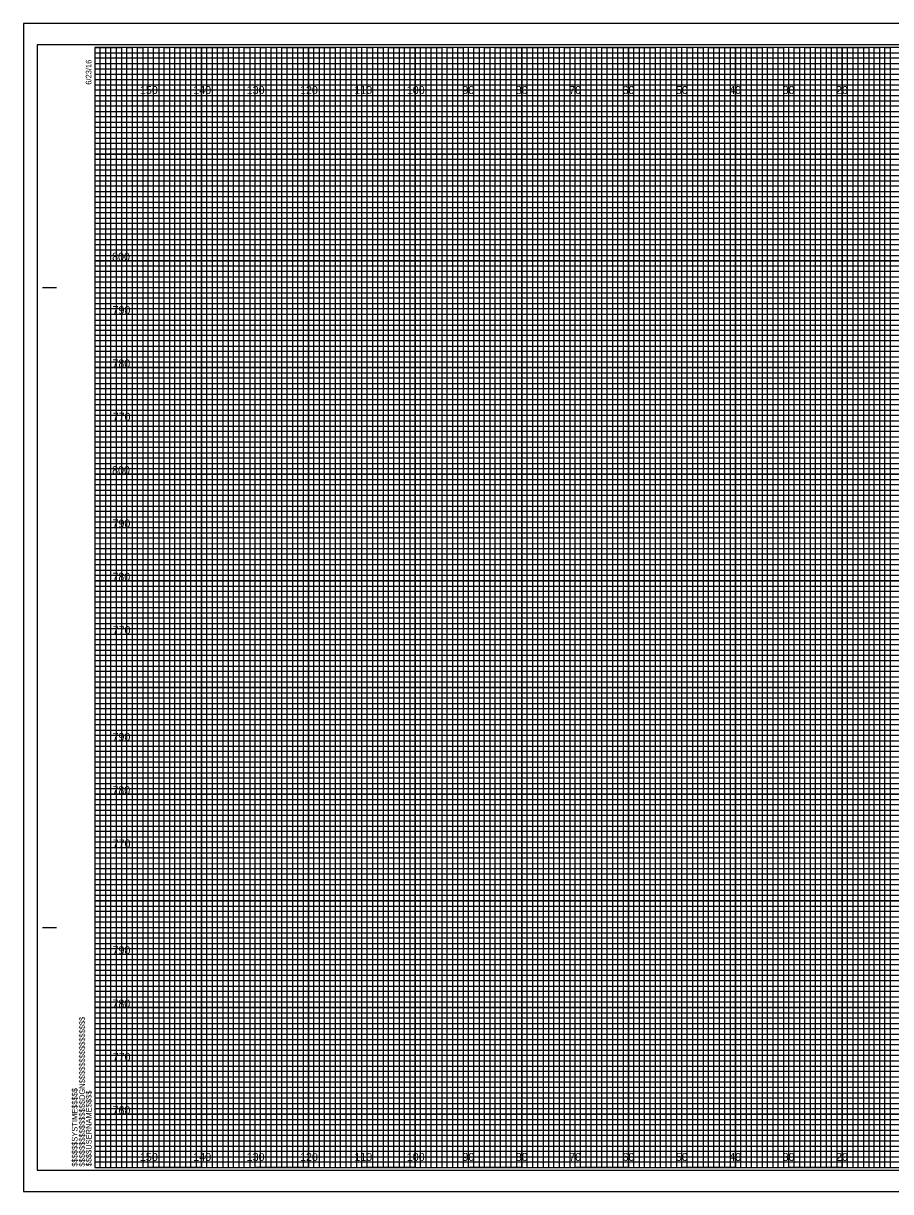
# Model space of a CAD drawing. Extents: x -13 to 323, y -4 to 214.
# Drawn here: x -13.4 to 149.1, y -4.5 to 214.5 of the extents above; entities that cross this region are included whole.
import ezdxf

# ---------------------------------------------------------------- set-up
doc = ezdxf.new("R2010")
doc.units = 0
for name, color, linetype in [('Exist Cross Section Cell', 7, 'Continuous'), ('Exist XS Center Line Elevation Label', 7, 'Continuous'), ('Exist XS Ground Line', 7, 'Continuous'), ('Prop CMT Pvmt Course 2', 7, 'Continuous'), ('Prop CMT Pvmt Course 3', 7, 'Continuous'), ('Prop CMT Pvmt Surface', 7, 'Continuous'), ('Prop CMT Shld Paved Course 1', 7, 'Continuous'), ('Prop CMT Shld Paved Course 3', 7, 'Continuous'), ('Prop CMT Subgrade Earthwork', 7, 'Continuous'), ('Scratch_Level_1', 7, 'Continuous'), ('Scratch_Level_7', 7, 'Continuous')]:
    doc.layers.add(name, color=color, linetype=linetype)

msp = doc.modelspace()

# ---------------------------------------------------------------- linework, layer by layer
at = {"layer": 'Exist XS Center Line Elevation Label'}
for points in [[(0, 210), (5, 210), (5, 0), (15, 0), (15, 210), (25, 210), (25, 0), (35, 0), (35, 210), (45, 210), (45, 0), (55, 0), (55, 210), (65, 210), (65, 0), (75, 0), (75, 210), (85, 210), (85, 0), (95, 0), (95, 210), (105, 210), (105, 0), (115, 0), (115, 210), (125, 210), (125, 0), (135, 0), (135, 210), (145, 210), (145, 0), (155, 0)], [(0, 205), (275, 205)], [(0, 185), (320, 185), (320, 195), (0, 195)], [(0, 165), (320, 165), (320, 175), (0, 175)], [(0, 145), (320, 145), (320, 155), (0, 155)], [(0, 125), (320, 125), (320, 135), (0, 135)], [(0, 105), (320, 105), (320, 115), (0, 115)], [(0, 85), (320, 85), (320, 95), (0, 95)], [(0, 65), (320, 65), (320, 75), (0, 75)], [(0, 45), (320, 45), (320, 55), (0, 55)], [(0, 25), (320, 25), (320, 35), (0, 35)], [(0, 5), (320, 5), (320, 15), (0, 15)]]:
    msp.add_lwpolyline(points, dxfattribs=at)
at = {"layer": 'Exist XS Ground Line'}
for p, q in [((10, 210), (0, 210)), ((10, 0), (10, 210)), ((30, 210), (20, 210)), ((20, 210), (20, 0)), ((30, 0), (30, 210)), ((50, 210), (40, 210)), ((40, 210), (40, 0)), ((50, 0), (50, 210)), ((70, 210), (60, 210)), ((60, 210), (60, 0)), ((70, 0), (70, 210)), ((90, 210), (80, 210)), ((80, 210), (80, 0)), ((90, 0), (90, 210)), ((110, 210), (100, 210)), ((100, 210), (100, 0)), ((110, 0), (110, 210)), ((130, 210), (120, 210)), ((120, 210), (120, 0)), ((130, 0), (130, 210)), ((150, 210), (140, 210)), ((140, 210), (140, 0)), ((20, 0), (10, 0)), ((40, 0), (30, 0)), ((60, 0), (50, 0)), ((80, 0), (70, 0)), ((100, 0), (90, 0)), ((120, 0), (110, 0)), ((140, 0), (130, 0))]:
    msp.add_line(p, q, dxfattribs=at)
for points in [[(0, 200), (320, 200), (320, 190), (0, 190)], [(0, 180), (320, 180), (320, 170), (0, 170)], [(0, 160), (320, 160), (320, 150), (0, 150)], [(0, 140), (320, 140), (320, 130), (0, 130)], [(0, 120), (320, 120), (320, 110), (0, 110)], [(0, 100), (320, 100), (320, 90), (0, 90)], [(0, 80), (320, 80), (320, 70), (0, 70)], [(0, 60), (320, 60), (320, 50), (0, 50)], [(0, 40), (320, 40), (320, 30), (0, 30)], [(0, 20), (320, 20), (320, 10), (0, 10)]]:
    msp.add_lwpolyline(points, dxfattribs=at)
at = {"layer": 'Prop CMT Pvmt Course 2'}
msp.add_lwpolyline([(-10.8, -0.5), (322.4, -0.5), (322.4, 210.5), (-10.8, 210.5)], close=True, dxfattribs=at)
at = {"layer": 'Prop CMT Pvmt Course 3'}
for p, q in [((10, 0), (10, 210)), ((20, 0), (20, 210)), ((30, 0), (30, 210)), ((40, 0), (40, 210)), ((50, 0), (50, 210)), ((60, 0), (60, 210)), ((70, 0), (70, 210)), ((80, 0), (80, 210)), ((90, 0), (90, 210)), ((100, 0), (100, 210)), ((110, 0), (110, 210)), ((120, 0), (120, 210)), ((130, 0), (130, 210)), ((140, 0), (140, 210)), ((0, 200), (320, 200)), ((0, 190), (320, 190)), ((0, 180), (320, 180)), ((0, 170), (320, 170)), ((0, 160), (320, 160)), ((0, 150), (320, 150)), ((0, 140), (320, 140)), ((0, 130), (320, 130)), ((0, 120), (320, 120)), ((0, 110), (320, 110)), ((0, 100), (320, 100)), ((0, 90), (320, 90)), ((0, 80), (320, 80)), ((0, 70), (320, 70)), ((0, 60), (320, 60)), ((0, 50), (320, 50)), ((0, 40), (320, 40)), ((0, 30), (320, 30)), ((0, 20), (320, 20)), ((0, 10), (320, 10))]:
    msp.add_line(p, q, dxfattribs=at)
at = {"layer": 'Prop CMT Shld Paved Course 1'}
for points in [[(0, 0), (1, 0), (1, 210), (2, 210), (2, 0)], [(2, 0), (3, 0), (3, 210), (4, 210), (4, 0)], [(5, 0), (6, 0), (6, 210), (7, 210), (7, 0)], [(7, 0), (8, 0), (8, 210), (9, 210), (9, 0)], [(10, 0), (11, 0), (11, 210), (12, 210), (12, 0)], [(12, 0), (13, 0), (13, 210), (14, 210), (14, 0)], [(15, 0), (16, 0), (16, 210), (17, 210), (17, 0)], [(17, 0), (18, 0), (18, 210), (19, 210), (19, 0)], [(20, 0), (21, 0), (21, 210), (22, 210), (22, 0)], [(22, 0), (23, 0), (23, 210), (24, 210), (24, 0)], [(25, 0), (26, 0), (26, 210), (27, 210), (27, 0)], [(27, 0), (28, 0), (28, 210), (29, 210), (29, 0)], [(30, 0), (31, 0), (31, 210), (32, 210), (32, 0)], [(32, 0), (33, 0), (33, 210), (34, 210), (34, 0)], [(35, 0), (36, 0), (36, 210), (37, 210), (37, 0)], [(37, 0), (38, 0), (38, 210), (39, 210), (39, 0)], [(40, 0), (41, 0), (41, 210), (42, 210), (42, 0)], [(42, 0), (43, 0), (43, 210), (44, 210), (44, 0)], [(45, 0), (46, 0), (46, 210), (47, 210), (47, 0)], [(47, 0), (48, 0), (48, 210), (49, 210), (49, 0)], [(50, 0), (51, 0), (51, 210), (52, 210), (52, 0)], [(52, 0), (53, 0), (53, 210), (54, 210), (54, 0)], [(55, 0), (56, 0), (56, 210), (57, 210), (57, 0)], [(57, 0), (58, 0), (58, 210), (59, 210), (59, 0)], [(60, 0), (61, 0), (61, 210), (62, 210), (62, 0)], [(62, 0), (63, 0), (63, 210), (64, 210), (64, 0)], [(65, 0), (66, 0), (66, 210), (67, 210), (67, 0)], [(67, 0), (68, 0), (68, 210), (69, 210), (69, 0)], [(70, 0), (71, 0), (71, 210), (72, 210), (72, 0)], [(72, 0), (73, 0), (73, 210), (74, 210), (74, 0)], [(75, 0), (76, 0), (76, 210), (77, 210), (77, 0)], [(77, 0), (78, 0), (78, 210), (79, 210), (79, 0)], [(80, 0), (81, 0), (81, 210), (82, 210), (82, 0)], [(82, 0), (83, 0), (83, 210), (84, 210), (84, 0)], [(85, 0), (86, 0), (86, 210), (87, 210), (87, 0)], [(87, 0), (88, 0), (88, 210), (89, 210), (89, 0)], [(90, 0), (91, 0), (91, 210), (92, 210), (92, 0)], [(92, 0), (93, 0), (93, 210), (94, 210), (94, 0)], [(95, 0), (96, 0), (96, 210), (97, 210), (97, 0)], [(97, 0), (98, 0), (98, 210), (99, 210), (99, 0)], [(100, 0), (101, 0), (101, 210), (102, 210), (102, 0)], [(102, 0), (103, 0), (103, 210), (104, 210), (104, 0)], [(105, 0), (106, 0), (106, 210), (107, 210), (107, 0)], [(107, 0), (108, 0), (108, 210), (109, 210), (109, 0)], [(110, 0), (111, 0), (111, 210), (112, 210), (112, 0)], [(112, 0), (113, 0), (113, 210), (114, 210), (114, 0)], [(115, 0), (116, 0), (116, 210), (117, 210), (117, 0)], [(117, 0), (118, 0), (118, 210), (119, 210), (119, 0)], [(120, 0), (121, 0), (121, 210), (122, 210), (122, 0)], [(122, 0), (123, 0), (123, 210), (124, 210), (124, 0)], [(125, 0), (126, 0), (126, 210), (127, 210), (127, 0)], [(127, 0), (128, 0), (128, 210), (129, 210), (129, 0)], [(130, 0), (131, 0), (131, 210), (132, 210), (132, 0)], [(132, 0), (133, 0), (133, 210), (134, 210), (134, 0)], [(135, 0), (136, 0), (136, 210), (137, 210), (137, 0)], [(137, 0), (138, 0), (138, 210), (139, 210), (139, 0)], [(140, 0), (141, 0), (141, 210), (142, 210), (142, 0)], [(142, 0), (143, 0), (143, 210), (144, 210), (144, 0)], [(145, 0), (146, 0), (146, 210), (147, 210), (147, 0)], [(147, 0), (148, 0), (148, 210), (149, 210), (149, 0)]]:
    msp.add_lwpolyline(points, dxfattribs=at)
at = {"layer": 'Prop CMT Shld Paved Course 3'}
msp.add_lwpolyline([(-13.4, -4.5), (323.3, -4.5), (323.3, 214.5), (-13.4, 214.5)], close=True, dxfattribs=at)
at = {"layer": 'Prop CMT Subgrade Earthwork'}
for p, q in [((323.3, 214.5), (-13.4, 214.5)), ((-13.4, 214.5), (-13.4, -4.5)), ((-13.4, -4.5), (323.3, -4.5))]:
    msp.add_line(p, q, dxfattribs=at)
at = {"layer": 'Scratch_Level_1'}
for p, q in [((0, 209), (260, 209)), ((260, 207.98), (0, 207.98)), ((0, 207.98), (0, 207)), ((0, 207), (260, 207)), ((260, 205.89), (0, 205.89)), ((0, 205.89), (0, 204)), ((0, 204), (320, 204))]:
    msp.add_line(p, q, dxfattribs=at)
for points in [[(0, 203), (270, 203), (320, 203), (320, 202), (0, 202)], [(0, 201), (320, 201), (320, 199), (0, 199)], [(0, 198), (320, 198), (320, 197), (0, 196.98)], [(0, 196), (320, 196), (320, 194), (0, 194)], [(0, 193), (320, 193), (320, 192), (0, 192)], [(0, 191), (320, 191), (320, 189), (0, 189)], [(0, 188), (320, 188), (320, 187), (0, 187)], [(0, 186), (320, 186), (320, 184), (0, 184)], [(0, 183), (320, 183), (320, 182), (0, 182)], [(0, 181), (320, 181), (320, 179), (0, 179)], [(0, 178), (320, 178), (320, 177), (0, 177)], [(0, 176), (320, 176), (320, 173.95), (320, 173), (320, 172), (0, 172)], [(0, 174), (320, 174), (320, 173), (0, 173)], [(0, 171), (320, 171), (320, 169), (0, 169.03)], [(0, 169.03), (320, 169), (320, 168), (0, 168)], [(0, 167), (320, 167), (320, 166), (0, 166)], [(0, 164), (320, 164), (320, 163), (0, 163)], [(0, 162), (320, 162), (320, 161), (0, 161)], [(-0.07, 158.89), (320, 158.89), (320, 157.88), (-0.07, 157.88)], [(0, 157), (320, 157), (320, 156), (0, 156)], [(0, 154), (320, 154), (320, 153), (0, 153)], [(0, 152), (320, 152), (320, 151), (0, 151)], [(0, 149), (320, 149), (320, 148), (0, 148)], [(0, 147), (320, 147), (320, 146), (0, 146)], [(0, 144), (320, 144), (320, 143), (0, 143)], [(0, 142), (320, 142), (320, 141), (0, 141)], [(0, 139), (320, 139), (319.99, 137.98), (0, 138)], [(0, 137), (320, 137), (320, 136), (0, 136)], [(0, 134), (320, 134), (320, 133), (0, 133)], [(0, 132), (320, 132), (320, 131), (0, 131)], [(0, 129), (320, 129), (320, 128), (0, 128)], [(0, 127), (320, 127), (320, 126), (0, 126)], [(0, 124), (320, 124), (320, 123), (0, 123)], [(0, 122), (320, 122), (320, 121), (0, 121)], [(0, 119), (320, 119), (320, 118), (0, 118)], [(0, 116.99), (320.07, 116.91), (320, 116), (0, 116)], [(0, 114), (320, 114), (320, 113), (0, 113)], [(0, 112), (320, 112), (320, 111), (0, 111)], [(0, 109), (320, 109), (320, 108), (0, 108)], [(0, 107), (320, 107), (320, 106), (0, 106)], [(0, 104), (320, 104), (320, 103), (0, 103)], [(0, 102), (320, 102), (320, 101), (0, 101)], [(0, 99), (320, 99), (320, 98), (0, 98)], [(0, 97), (320, 97), (320, 96), (0, 96)], [(0, 94), (320, 94), (320, 93), (0, 93)], [(0, 92), (320, 92), (320, 91), (0, 91)], [(0, 89), (320, 89), (320, 88), (0, 88)], [(0, 87), (320, 87), (320, 86), (0, 86)], [(0, 84), (320, 84), (320, 83), (0, 83)], [(0, 82), (320, 82), (320, 81), (0, 81)], [(0, 79), (320, 79), (319.99, 77.98), (0, 78)], [(0, 77), (320, 77), (320, 76), (0, 76)], [(0, 74), (320, 74), (320, 73), (0, 73)], [(0, 72), (320, 72), (320, 71), (0, 71)], [(0, 69), (320, 69), (320, 68), (0, 68)], [(0, 67), (320, 67), (320, 66), (0, 66)], [(0, 64), (320, 64), (320, 63), (0, 63)], [(0, 62), (320, 62), (320, 61), (0, 61)], [(0, 59), (320, 59), (320, 58), (0, 58)], [(0, 56.99), (320.07, 56.91), (320, 56), (0, 56)], [(0, 54), (320, 54), (320, 53), (0, 53)], [(0, 52), (320, 52), (320, 51), (0, 51)], [(0, 49), (320, 49), (320, 48), (0, 48)], [(0, 47), (320, 47), (320, 46), (0, 46)], [(0, 44), (320, 44), (320, 43), (0, 43)], [(0, 42), (320, 42), (320, 41), (0, 41)], [(0, 39), (320, 39), (320, 38), (0, 38)], [(0, 37), (320, 37), (320, 36), (0, 36)], [(0, 34), (320, 34), (320, 33), (0, 33)], [(0, 32), (320, 32), (320, 31), (0, 31)], [(0, 29), (320, 29), (320, 28), (0, 28)], [(0, 27), (320, 27), (320, 26), (0, 26)], [(0, 24), (320, 24), (320, 23), (0, 23)], [(0, 22), (320, 22), (320, 21), (0, 21)], [(0, 19), (320, 19), (320, 18), (0, 18)], [(0, 17), (320, 17), (320, 16), (0, 16)], [(0, 14), (320, 14), (320, 13), (0, 13)], [(0, 12), (320, 12), (320, 11), (0, 11)], [(0, 9), (320, 9), (320, 8), (0, 8)], [(0, 7), (320, 7), (320, 6), (0, 6)], [(0, 4), (320, 4), (320, 3), (0, 3)], [(0, 2), (320, 2), (320, 1), (0, 1)]]:
    msp.add_lwpolyline(points, dxfattribs=at)
at = {"layer": 'Scratch_Level_7'}
for p, q in [((-9.8, 165), (-7.3, 165)), ((-9.7, 165), (-7.2, 165)), ((-9.8, 45), (-7.3, 45)), ((-9.7, 45), (-7.2, 45)), ((0, 0), (0, 0)), ((0, 0), (0, 0)), ((0, 0), (0, 0)), ((0, 0), (0, 0)), ((0, 0), (0, 0)), ((0, 0), (0, 0)), ((0, 0), (0, 0))]:
    msp.add_line(p, q, dxfattribs=at)
msp.add_lwpolyline([(320, 210), (0, 210), (0, 0), (320, 0)], close=True, dxfattribs=at)

# ---------------------------------------------------------------- texts
at = {"layer": 'Exist Cross Section Cell'}
for s, p in [('150', (8.44, 201.25)), ('140', (18.44, 201.25)), ('130', (28.44, 201.25)), ('120', (38.44, 201.25)), ('110', (48.62, 201.25)), ('100', (58.44, 201.25)), ('90', (68.86, 201.25)), ('80', (78.86, 201.25)), ('70', (88.86, 201.25)), ('60', (98.86, 201.25)), ('50', (108.86, 201.25)), ('40', (118.86, 201.25)), ('30', (128.86, 201.25)), ('20', (138.86, 201.25)), ('150', (8.44, 1.25)), ('140', (18.44, 1.25)), ('130', (28.44, 1.25)), ('120', (38.44, 1.25)), ('110', (48.62, 1.25)), ('100', (58.44, 1.25)), ('90', (68.86, 1.25)), ('80', (78.86, 1.25)), ('70', (88.86, 1.25)), ('60', (98.86, 1.25)), ('50', (108.86, 1.25)), ('40', (118.86, 1.25)), ('30', (128.86, 1.25)), ('20', (138.86, 1.25))]:
    msp.add_text(s, height=1.5, dxfattribs=at).set_placement(p)
at = {"layer": 'Prop CMT Pvmt Surface'}
for s, p in [('800', (3.22, 170)), ('790', (3.3, 160)), ('780', (3.28, 150)), ('770', (3.33, 140)), ('800', (3.22, 130)), ('790', (3.3, 120)), ('780', (3.28, 110)), ('770', (3.33, 100)), ('790', (3.3, 80)), ('780', (3.28, 70)), ('770', (3.33, 60)), ('790', (3.3, 40)), ('780', (3.28, 30)), ('770', (3.33, 20)), ('760', (3.3, 10))]:
    msp.add_text(s, height=1.5, dxfattribs=at).set_placement(p)
at = {"layer": 'Scratch_Level_7'}
for s, p in [('6/23/16', (-0.65, 203)), ('$$$$$$$$$$$$$$$$DGN$$$$$$$$$$$$$$$$', (-1.88, 0.18)), ('$$$$$$SYSTIME$$$$$', (-3.26, 0.18)), ('$$$$USERNAME$$$$', (-0.62, 0.23))]:
    msp.add_text(s, height=1.05, rotation=90, dxfattribs=at).set_placement(p)

doc.saveas('drawing.dxf')
